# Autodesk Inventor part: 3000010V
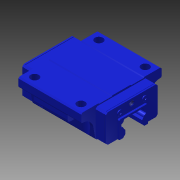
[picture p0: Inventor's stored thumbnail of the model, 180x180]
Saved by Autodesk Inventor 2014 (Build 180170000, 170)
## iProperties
Company: NHTSA/VRTC
Created: 2012-02
Part Number: 3000010V
Catalog Web Link: www.cadenas.de
Description: FLANGE TYPE - HEAVY LOAD SLIDER
Document SubType Name: Modeling
Designer: Dave Walker
Material: Steel
Density: 7.85 g/cm^3
Stock Number: HSR30BSSB-M6F Slider
Mass: 1378.95 g
Surface Area: 311.665 cm^2
Volume: 175.663 cm^3
Project: CHILD SIDE IMPACT SLED
Appearance: Blue - Wall Paint - Glossy
NB: HSR30BSSB-M6F Slider
NN: Flange Type - Heavy Load HSR-B Slider
NBSYN: HSR30BSSB-M6F Slider
LINA: HSR30BSSB-M6F Slider
MN: HSR30B
SO: SS
SO1: 'SS','SS- With end, side seals','UU','UU- With end seals (on both ends)','DD','DD- With double, side, inner seals','ZZ','ZZ- With end, side, inner seals and met
GPJ: B-M6F
M: 42.00
W: 90.00
L: 98.00
B: 72.00
C: 52.00
H: 9.00
L1: 70.40
SST: 18.000
T: 9.000
T1: 10.000
K: 35.00
N: 7.00
H3: 7.000
W1: 28.000
M1: 26.000
LX: 98.000
SH: 58.00
Z1: 2.000
Z2: 2.000
GPJ1: <'B-M6F','B-M6F'>,'', 'None', 'A-M6F','A-M6F','C-M6F','C-M6F', 'LF-A','LF-A','LF-B','LF-B', 'SF-A','SF-A','SF-B','SF-B'
L4: 0.950
ND: 4.000
SE: 58.000
SE3: 2.000
SE4: 2.000
V: 38.000
V1: 56.000
V2: 4.370
V3: 1.283
ST: 31.717
SE1: 31.717
SU: 1.283
SE2: 1.283
STT: 2.000
SEE1: 2.000
UP: 1.283
QZX: '','No','QZ','Yes'
LP: 2.000
L3: 10.300
L5: 2.000
S2: 7.000
L7: 38.000
XX: 28.000
R: 2.850
YY: 26.000
SS: 2.500
ZZ: 0.000
GPJX: 2.000
KT: DUMMY
SUPPLIER: THK
ARTICLENO: HSR30BSSB-M6F Slider
BOMINFO: HSR30BSSB-M6F Slider
CREATOR: CADENAS GmbH
PSOL_IDENT_0: {\\10.0.0.251\ps_data\23d-libs\thk\linear_motion_systems\lm_guide\lm_guide\lm_guide_hsr\four_through
PSOL_IDENT_1: _hole_type\hsr_b\hsr_b_slider.prj},222 {VTYP=3D},{NB=HSR30BSSB-M6F Slider},{LINA=HSR30BSSB-M6F Slide
PSOL_IDENT_2: r},{NN=Flange Type - Heavy Load HSR-B Slider},{DATE=24.06.2011 05:36:03},{GEOMDATE=24.06.2011 05:35:
PSOL_IDENT_3: 00},{VERSION=},{LINEID=70},{LINESUBID=-1},{WBVAR=SO,QZ,GPJ}  {NB=HSR30BSSB-M6F Slider},{LINA=HSR30BS
PSOL_IDENT_4: SB-M6F Slider},{KT=DUMMY},{MN=HSR30B},{SO=SS},{QZ=},{SO1='SS','SS- With end, side seals','UU','UU- W
PSOL_IDENT_5: ith end seals (on both ends)','DD','DD- With double, side, inner seals','ZZ','ZZ- With end, side, in
PSOL_IDENT_6: ner seals and metal scrapers','KK','KK- With double, side, inner seals and metal scrapers','SSHH','S
PSOL_IDENT_7: SHH- With end, side, inner seals and LaCS','DDHH','DDHH- With double, side, inner seals and LaCS','Z
PSOL_IDENT_8: ZHH','ZZHH- With end, side, inner seals and metal scrapers and LaCS','KKHH','KKHH- With double, side
PSOL_IDENT_9: , inner seals and metal scrapers and LaCS'},{GPJ=B-M6F},{M=42.00},{W=90.00},{L=98.00},{B=72.00},{C=5
PSOL_IDENT_10: 2.00},{H=9.00},{L1=70.40},{SST=18.000},{T=9.000},{T1=10.000},{K=35.00},{N=7.00},{H3=7.000},{W1=28.00
PSOL_IDENT_11: 0},{M1=26.000},{LX=98},{SH=58.00},{Z1=2.000},{Z2=2.000},{GPJ1=<'B-M6F','B-M6F'>,'', 'None', 'A-M6F',
PSOL_IDENT_12: 'A-M6F','C-M6F','C-M6F', 'LF-A','LF-A','LF-B','LF-B', 'SF-A','SF-A','SF-B','SF-B'},{L4=0.95},{ND=4.0
PSOL_IDENT_13: 00},{SE=58.000},{SE3=2.000},{SE4=2.000},{V=38.000},{V1=56.000},{V2=4.370},{V3=1.283},{ST=31.717},{SE
PSOL_IDENT_14: 1=31.717},{SU=1.283},{SE2=1.283},{STT=2.000},{SEE1=2.000},{UP=1.283},{QZX='','No','QZ','Yes'},{LP=2}
PSOL_IDENT_15: ,{L3=10.300},{L5=2},{S2=7.000},{L7=38.000},{XX=28.000},{R=2.850},{YY=26.000},{SS=2.500},{ZZ=0.000},{
PSOL_IDENT_16: GPJX=2}
Title: Linear Rail Slider
Author: Dave Walker
Subject: Child Side Impact Sled
Comments: Reference Supplier: THK - http://www.thk.com/us/index.html Linear Rail System:  HSR-30B
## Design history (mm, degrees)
sketch "Sketch_17"
  geometry: L1 (26, 45)-(24.268, 44); L2 (24.268, 44)-(20, 44); L3 (17, 41)-(17, 34.343); L4 (14.514, 31.388)-(3.269, 29.432); L5 (0.783, 26.477)-(0.783, 22); L6 (0.783, 22)-(1.283, 22); L7 (1.283, 22)-(1.283, -22); L8 (1.283, -22)-(0.783, -22); L9 (0.783, -22)-(0.783, -26.477); L10 (3.269, -29.432)-(14.514, -31.388); L11 (17, -34.343)-(17, -41); L12 (20, -44)-(24.268, -44); L13 (24.268, -44)-(26, -45); L14 (26, -45)-(33.6, -45); L15 (33.6, -45)-(35, -43.6); L16 (35, -43.6)-(35, -25.8); L17 (35, -25.8)-(34.2, -25); L18 (34.2, -25)-(34.2, -11); L19 (34.2, -11)-(35, -10.2); L20 (35, -10.2)-(35, 10.2); L21 (35, 10.2)-(34.2, 11); L22 (34.2, 11)-(34.2, 25); L23 (34.2, 25)-(35, 25.8); L24 (35, 25.8)-(35, 43.6); L25 (35, 43.6)-(33.6, 45); L26 (33.6, 45)-(26, 45); A1 r 3 centre (20, 41) between (20, 44) and (17, 41); A2 r 3 centre (14, 34.343) between (14.514, 31.388) and (17, 34.343); A3 r 3 centre (3.783, 26.477) between (3.269, 29.432) and (0.783, 26.477); A4 r 3 centre (3.783, -26.477) between (0.783, -26.477) and (3.269, -29.432); A5 r 3 centre (14, -34.343) between (17, -34.343) and (14.514, -31.388); A6 r 3 centre (20, -41) between (17, -41) and (20, -44)
  constraints: 52 end point, 12 point on circle, 6 centre point
extrude "Extrusion1" join sketch "Sketch_17" stored distance "d0" = 70.4; taper "d1" = 0 deg
sketch "Sketch_100"
  geometry: L1 (29, 0.783)-(45, 0.783); L2 (45, 0.783)-(45, 25); L3 (45, 25)-(43.725, 25); L4 (31.41, 14.642)-(29, 0.783); A1 r 12.5 centre (43.725, 12.5) between (43.725, 25) and (31.41, 14.642)
  constraints: 8 end point, 2 point on circle, 1 centre point
extrude "Extrusion2" cut sketch "Sketch_100" distance "d2" = 16.2; taper "d3" = 0 deg
sketch "Sketch_101"
  geometry: L1 (-45, 0.783)-(-29, 0.783); L2 (-29, 0.783)-(-31.41, 14.642); L3 (-43.725, 25)-(-45, 25); L4 (-45, 25)-(-45, 0.783); A1 r 12.5 centre (-43.725, 12.5) between (-31.41, 14.642) and (-43.725, 25)
  constraints: 8 end point, 2 point on circle, 1 centre point
extrude "Extrusion3" cut sketch "Sketch_101" distance "d4" = 16.2; taper "d5" = 0 deg
sketch "Sketch_102"
  geometry: L1 (-45, 0.783)-(-29, 0.783); L2 (-29, 0.783)-(-31.41, 14.642); L3 (-43.725, 25)-(-45, 25); L4 (-45, 25)-(-45, 0.783); A1 r 12.5 centre (-43.725, 12.5) between (-31.41, 14.642) and (-43.725, 25)
  constraints: 8 end point, 2 point on circle, 1 centre point
extrude "Extrusion4" cut sketch "Sketch_102" distance "d6" = 16.2; taper "d7" = 0 deg
sketch "Sketch_103"
  geometry: L1 (29, 0.783)-(45, 0.783); L2 (45, 0.783)-(45, 25); L3 (45, 25)-(43.725, 25); L4 (31.41, 14.642)-(29, 0.783); A1 r 12.5 centre (43.725, 12.5) between (43.725, 25) and (31.41, 14.642)
  constraints: 8 end point, 2 point on circle, 1 centre point
extrude "Extrusion5" cut sketch "Sketch_103" distance "d8" = 16.2; taper "d9" = 0 deg
sketch "Sketch_28"
  geometry: L1 (-26, 35)-(-26, 25); L2 (-26, 25)-(-30.5, 25); L3 (-30.5, 25)-(-30.5, 35); L4 (-30.5, 35)-(-26, 35); L5 (-26, 35)-(-26, 25)
  constraints: 10 end point
revolve "Revolution1" sketch "Sketch_28" stored, may be unused: angle "d10" = 360 deg
pattern_linear "Rectangular Pattern1" dims "d13" = 52, "d16" = 72
sketch "Sketch_60"
  geometry: L1 (-33, -53.5)-(-19, -53.5); L2 (-19, -53.5)-(-19, -36); L3 (-33, -36)-(-33, -53.5); A1 r 7 centre (-26, -36) between (-19, -36) and (-33, -36)
  constraints: 6 end point, 2 point on circle, 1 centre point
extrude "Extrusion6" cut sketch "Sketch_60" distance "d17" = 35; taper "d18" = 0 deg
sketch "Sketch_61"
  geometry: L1 (-33, 53.5)-(-33, 36); L2 (-19, 36)-(-19, 53.5); L3 (-19, 53.5)-(-33, 53.5); A1 r 7 centre (-26, 36) between (-33, 36) and (-19, 36)
  constraints: 6 end point, 2 point on circle, 1 centre point
extrude "Extrusion7" cut sketch "Sketch_61" distance "d19" = 25; taper "d20" = 0 deg
sketch "Sketch_62"
  geometry: L1 (19, -53.5)-(33, -53.5); L2 (33, -53.5)-(33, -36); L3 (19, -36)-(19, -53.5); A1 r 7 centre (26, -36) between (33, -36) and (19, -36)
  constraints: 6 end point, 2 point on circle, 1 centre point
extrude "Extrusion8" cut sketch "Sketch_62" distance "d21" = 25; taper "d22" = 0 deg
sketch "Sketch_63"
  geometry: L1 (19, 53.5)-(19, 36); L2 (33, 36)-(33, 53.5); L3 (33, 53.5)-(19, 53.5); A1 r 7 centre (26, 36) between (19, 36) and (33, 36)
  constraints: 6 end point, 2 point on circle, 1 centre point
extrude "Extrusion9" cut sketch "Sketch_63" distance "d23" = 25; taper "d24" = 0 deg
sketch "Sketch_7"
  geometry: L1 (-29, 31)-(-29, 3.083); L2 (-29, 3.083)-(-27.2, 1.283); L3 (-27.2, 1.283)-(27.2, 1.283); L4 (27.2, 1.283)-(29, 3.083); L5 (29, 3.083)-(29, 31); L6 (29, 31)-(27, 33); L7 (27, 33)-(-27, 33); L8 (-27, 33)-(-29, 31)
  constraints: 16 end point
extrude "Extrusion10" join sketch "Sketch_7" distance "d25" = 10.3; taper "d26" = 0 deg
sketch "Sketch_2"
  geometry: L1 (-29, 31)-(-29, 3.283); L2 (-29, 3.283)-(-27, 1.283); L3 (-27, 1.283)-(27, 1.283); L4 (27, 1.283)-(29, 3.283); L5 (29, 3.283)-(29, 31); L6 (29, 31)-(27, 33); L7 (27, 33)-(-27, 33); L8 (-27, 33)-(-29, 31)
  constraints: 16 end point
extrude "Extrusion11" join sketch "Sketch_2" distance "d27" = 3.5; taper "d28" = 0 deg
sketch "Sketch_8"
  geometry: L1 (-29, 31)-(-29, 3.083); L2 (-29, 3.083)-(-27.2, 1.283); L3 (-27.2, 1.283)-(27.2, 1.283); L4 (27.2, 1.283)-(29, 3.083); L5 (29, 3.083)-(29, 31); L6 (29, 31)-(27, 33); L7 (27, 33)-(-27, 33); L8 (-27, 33)-(-29, 31)
  constraints: 16 end point
extrude "Extrusion12" join sketch "Sketch_8" distance "d29" = 10.3; taper "d30" = 0 deg
sketch "Sketch_9"
  geometry: L1 (-29, 31)-(-29, 3.283); L2 (-29, 3.283)-(-27, 1.283); L3 (-27, 1.283)-(27, 1.283); L4 (27, 1.283)-(29, 3.283); L5 (29, 3.283)-(29, 31); L6 (29, 31)-(27, 33); L7 (27, 33)-(-27, 33); L8 (-27, 33)-(-29, 31)
  constraints: 16 end point
extrude "Extrusion13" join sketch "Sketch_9" distance "d31" = 3.5; taper "d32" = 0 deg
sketch "Sketch_1"
  geometry: L1 (-29, 0)-(29, 0); L2 (29, 0)-(29, 35); L3 (29, 35)-(-29, 35); L4 (-29, 35)-(-29, 0)
  constraints: 8 end point
extrude "Extrusion14" cut sketch "Sketch_1" distance "d33" = 2; taper "d34" = 0 deg
sketch "Sketch_6"
  geometry: L1 (-29, 0)-(29, 0); L2 (29, 0)-(29, 35); L3 (29, 35)-(-29, 35); L4 (-29, 35)-(-29, 0)
  constraints: 8 end point
extrude "Extrusion15" cut sketch "Sketch_6" distance "d35" = 2; taper "d36" = 0 deg
sketch "Sketch_20"
  geometry: L1 (-16, 20)-(-16, 1.283); L2 (-16, 1.283)-(16, 1.283); L3 (16, 1.283)-(16, 20); L4 (16, 20)-(15, 21); L5 (15, 21)-(-15, 21); L6 (-15, 21)-(-16, 20)
  constraints: 12 end point
extrude "Extrusion16" join sketch "Sketch_20" distance "d37" = 2; taper "d38" = 0 deg
sketch "Sketch_21"
  geometry: L1 (-16, 20)-(-16, 1.283); L2 (-16, 1.283)-(16, 1.283); L3 (16, 1.283)-(16, 20); L4 (16, 20)-(15, 21); L5 (15, 21)-(-15, 21); L6 (-15, 21)-(-16, 20)
  constraints: 12 end point
extrude "Extrusion17" join sketch "Sketch_21" distance "d39" = 2; taper "d40" = 0 deg
sketch "Sketch_64"
  geometry: L1 (15.215, 14)-(12.779, 14); L2 (12.779, 14)-(12.31, 13.531); L3 (9.779, 11)-(8.079, 9.3); L4 (8.079, 9.3)-(4, 9.3); L5 (4, 9.3)-(-0.7, 14); L6 (-0.7, 14)-(-5.5, 14); L7 (-5.5, 14)-(-7, 12.5); L8 (-7, 12.5)-(-7, 7.75); L9 (-7, 7.75)-(-6.5, 7.25); L10 (-6.5, 7.25)-(-6.5, 3.75); L11 (-6.5, 3.75)-(-7, 3.25); L12 (-7, 3.25)-(-7, -3.25); L13 (-7, -3.25)-(-6.5, -3.75); L14 (-6.5, -3.75)-(-6.5, -7.25); L15 (-6.5, -7.25)-(-7, -7.75); L16 (-7, -7.75)-(-7, -12.5); L17 (-7, -12.5)-(-5.5, -14); L18 (-5.5, -14)-(-0.7, -14); L19 (-0.7, -14)-(4, -9.3); L20 (4, -9.3)-(8.079, -9.3); L21 (8.079, -9.3)-(9.779, -11); L22 (12.31, -13.531)-(12.779, -14); L23 (12.779, -14)-(15.215, -14); L24 (15.215, -14)-(15.69, -13.525); L25 (18.215, -11)-(19, -10.215); L26 (19, -10.215)-(19, 10.215); L27 (19, 10.215)-(18.215, 11); L28 (15.69, 13.525)-(15.215, 14); A1 r 2.89 centre (9.44, 13.87) between (9.779, 11) and (12.31, 13.531); A2 r 2.89 centre (9.44, -13.87) between (12.31, -13.531) and (9.779, -11); A3 r 2.89 centre (18.56, -13.87) between (18.215, -11) and (15.69, -13.525); A4 r 2.89 centre (18.56, 13.87) between (15.69, 13.525) and (18.215, 11)
  constraints: 56 end point, 8 point on circle, 4 centre point
extrude "Extrusion18" cut sketch "Sketch_64" stored distance "d41" = 98; taper "d42" = 0 deg
sketch "Sketch_4"
  geometry: L1 (47.95, 26)-(47, 26); L2 (47, 26)-(47, 28.85); L3 (47, 28.85)-(47.713, 28.85); L4 (47.95, 28.613)-(47.95, 26); L5 (47.95, 26)-(47, 26); A1 r 0.237 centre (47.713, 28.613) between (47.95, 28.613) and (47.713, 28.85)
  constraints: 10 end point, 2 point on circle, 1 centre point
revolve "Revolution2" sketch "Sketch_4" stored, may be unused: angle "d43" = 360 deg
sketch "Sketch_14"
  geometry: L1 (-47, 26)-(-47.95, 26); L2 (-47.95, 26)-(-47.95, 28.613); L3 (-47.713, 28.85)-(-47, 28.85); L4 (-47, 28.85)-(-47, 26); L5 (-47, 26)-(-47.95, 26); A1 r 0.237 centre (-47.713, 28.613) between (-47.713, 28.85) and (-47.95, 28.613)
  constraints: 10 end point, 2 point on circle, 1 centre point
revolve "Revolution3" sketch "Sketch_14" stored, may be unused: angle "d44" = 360 deg
sketch "Sketch_15"
  geometry: L1 (47.95, 26)-(47, 26); L2 (47, 26)-(47, 28.85); L3 (47, 28.85)-(47.713, 28.85); L4 (47.95, 28.613)-(47.95, 26); L5 (47.95, 26)-(47, 26); A1 r 0.237 centre (47.713, 28.613) between (47.95, 28.613) and (47.713, 28.85)
  constraints: 10 end point, 2 point on circle, 1 centre point
revolve "Revolution4" sketch "Sketch_15" stored, may be unused: angle "d45" = 360 deg
sketch "Sketch_16"
  geometry: L1 (-47, 26)-(-47.95, 26); L2 (-47.95, 26)-(-47.95, 28.613); L3 (-47.713, 28.85)-(-47, 28.85); L4 (-47, 28.85)-(-47, 26); L5 (-47, 26)-(-47.95, 26); A1 r 0.237 centre (-47.713, 28.613) between (-47.713, 28.85) and (-47.95, 28.613)
  constraints: 10 end point, 2 point on circle, 1 centre point
revolve "Revolution5" sketch "Sketch_16" stored, may be unused: angle "d46" = 360 deg
sketch "Sketch_24"
  geometry: L1 (12.75, 26.722)-(12.75, 25.278); L2 (12.75, 25.278)-(14, 24.557); L3 (14, 24.557)-(15.25, 25.278); L4 (15.25, 25.278)-(15.25, 26.722); L5 (15.25, 26.722)-(14, 27.443); L6 (14, 27.443)-(12.75, 26.722)
  constraints: 12 end point
extrude "Extrusion19" cut sketch "Sketch_24" distance "d47" = 0.475; taper "d48" = 0 deg
sketch "Sketch_25"
  geometry: L1 (-15.25, 26.722)-(-15.25, 25.278); L2 (-15.25, 25.278)-(-14, 24.557); L3 (-14, 24.557)-(-12.75, 25.278); L4 (-12.75, 25.278)-(-12.75, 26.722); L5 (-12.75, 26.722)-(-14, 27.443); L6 (-14, 27.443)-(-15.25, 26.722)
  constraints: 12 end point
extrude "Extrusion20" cut sketch "Sketch_25" distance "d49" = 0.475; taper "d50" = 0 deg
sketch "Sketch_26"
  geometry: L1 (12.75, 26.722)-(12.75, 25.278); L2 (12.75, 25.278)-(14, 24.557); L3 (14, 24.557)-(15.25, 25.278); L4 (15.25, 25.278)-(15.25, 26.722); L5 (15.25, 26.722)-(14, 27.443); L6 (14, 27.443)-(12.75, 26.722)
  constraints: 12 end point
extrude "Extrusion21" cut sketch "Sketch_26" distance "d51" = 0.475; taper "d52" = 0 deg
sketch "Sketch_27"
  geometry: L1 (-15.25, 26.722)-(-15.25, 25.278); L2 (-15.25, 25.278)-(-14, 24.557); L3 (-14, 24.557)-(-12.75, 25.278); L4 (-12.75, 25.278)-(-12.75, 26.722); L5 (-12.75, 26.722)-(-14, 27.443); L6 (-14, 27.443)-(-15.25, 26.722)
  constraints: 12 end point
extrude "Extrusion22" cut sketch "Sketch_27" distance "d53" = 0.475; taper "d54" = 0 deg
sketch "Sketch_12"
  geometry: L1 (-45.5, 33)-(-45.5, 32.5); L2 (-45.5, 32.5)-(-45, 33); L3 (-45, 33)-(-45.5, 33)
  constraints: 6 end point
extrude "Extrusion23" cut sketch "Sketch_12" stored distance "d55" = 58; taper "d56" = 0 deg
sketch "Sketch_13"
  geometry: L1 (45, 33)-(45.5, 32.5); L2 (45.5, 32.5)-(45.5, 33); L3 (45.5, 33)-(45, 33)
  constraints: 6 end point
extrude "Extrusion24" cut sketch "Sketch_13" stored distance "d57" = 58; taper "d58" = 0 deg
sketch "Sketch_90"
  geometry: L1 (-45, -29)-(-45.5, -28.5); L2 (-45.5, -28.5)-(-45.5, -29); L3 (-45.5, -29)-(-45, -29)
  constraints: 6 end point
extrude "Extrusion25" cut sketch "Sketch_90" distance "d59" = 35; taper "d60" = 0 deg
sketch "Sketch_91"
  geometry: L1 (45.5, -29)-(45.5, -28.5); L2 (45.5, -28.5)-(45, -29); L3 (45, -29)-(45.5, -29)
  constraints: 6 end point
extrude "Extrusion26" cut sketch "Sketch_91" distance "d61" = 35; taper "d62" = 0 deg
sketch "Sketch_92"
  geometry: L1 (-45, 29)-(-45.5, 29); L2 (-45.5, 29)-(-45.5, 28.5); L3 (-45.5, 28.5)-(-45, 29)
  constraints: 6 end point
extrude "Extrusion27" cut sketch "Sketch_92" distance "d63" = 35; taper "d64" = 0 deg
sketch "Sketch_93"
  geometry: L1 (45.5, 29)-(45, 29); L2 (45, 29)-(45.5, 28.5); L3 (45.5, 28.5)-(45.5, 29)
  constraints: 6 end point
extrude "Extrusion28" cut sketch "Sketch_93" distance "d65" = 35; taper "d66" = 0 deg
sketch "Sketch_74"
  geometry: L1 (47, 28)-(39.581, 28); L2 (39.581, 28)-(41, 30.459); L3 (41, 30.459)-(46.459, 30.459); L4 (46.459, 30.459)-(47, 31); L5 (47, 31)-(47, 28); L6 (47, 28)-(39.581, 28)
  constraints: 12 end point
revolve "Revolution6" sketch "Sketch_74" stored, may be unused: angle "d67" = 360 deg
thread "Thread1" dims "d68" = 5, "d69" = 1
sketch "Sketch_75"
  geometry: L1 (-39.581, 28)-(-47, 28); L2 (-47, 28)-(-47, 31); L3 (-47, 31)-(-46.459, 30.459); L4 (-46.459, 30.459)-(-41, 30.459); L5 (-41, 30.459)-(-39.581, 28); L6 (-39.581, 28)-(-47, 28)
  constraints: 12 end point
revolve "Revolution7" sketch "Sketch_75" stored, may be unused: angle "d70" = 360 deg
thread "Thread2" dims "d71" = 5, "d72" = 1
sketch "Sketch_38"
  geometry: L1 (28, 4.37)-(28, 0); L2 (28, 0)-(26.252, 0); L3 (25.815, 0.437)-(25.815, 4.37); L4 (25.815, 4.37)-(28, 4.37); L5 (28, 4.37)-(28, 0); A1 r 0.437 centre (26.252, 0.437) between (25.815, 0.437) and (26.252, 0)
  constraints: 10 end point, 2 point on circle, 1 centre point
sketch "Sketch_34"
  geometry: L1 (-28, 4.37)-(-28, 0); L2 (-28, 0)-(-29.748, 0); L3 (-30.185, 0.437)-(-30.185, 4.37); L4 (-30.185, 4.37)-(-28, 4.37); L5 (-28, 4.37)-(-28, 0); A1 r 0.437 centre (-29.748, 0.437) between (-30.185, 0.437) and (-29.748, 0)
  constraints: 10 end point, 2 point on circle, 1 centre point
revolve "Revolution8" sketch "Sketch_34" stored, may be unused: angle "d73" = 360 deg
sketch "Sketch_35"
  geometry: L1 (28, 4.37)-(28, 0); L2 (28, 0)-(26.252, 0); L3 (25.815, 0.437)-(25.815, 4.37); L4 (25.815, 4.37)-(28, 4.37); L5 (28, 4.37)-(28, 0); A1 r 0.437 centre (26.252, 0.437) between (25.815, 0.437) and (26.252, 0)
  constraints: 10 end point, 2 point on circle, 1 centre point
revolve "Revolution9" sketch "Sketch_35" stored, may be unused: angle "d74" = 360 deg
sketch "Sketch_37"
  geometry: L1 (-28, 4.37)-(-28, 0); L2 (-28, 0)-(-29.748, 0); L3 (-30.185, 0.437)-(-30.185, 4.37); L4 (-30.185, 4.37)-(-28, 4.37); L5 (-28, 4.37)-(-28, 0); A1 r 0.437 centre (-29.748, 0.437) between (-30.185, 0.437) and (-29.748, 0)
  constraints: 10 end point, 2 point on circle, 1 centre point
revolve "Revolution10" sketch "Sketch_37" stored, may be unused: angle "d75" = 360 deg
revolve "Revolution11" stored, may be unused: angle "d76" = 360 deg
node "4TRACK_XY"
node "4TRACK_YZ"
node "4TRACK_ZX"
node "4TRACK_X"
node "4TRACK_Y"
node "4TRACK_Z"
node "4TRACK_Center"
node "niple_XY"
node "niple_YZ"
node "niple_ZX"
node "niple_X"
node "niple_Y"
node "niple_Z"
node "niple_Center"
node "niple2_XY"
node "niple2_YZ"
node "niple2_ZX"
node "niple2_X"
node "niple2_Y"
node "niple2_Z"
node "niple2_Center"
body "Solid1"
